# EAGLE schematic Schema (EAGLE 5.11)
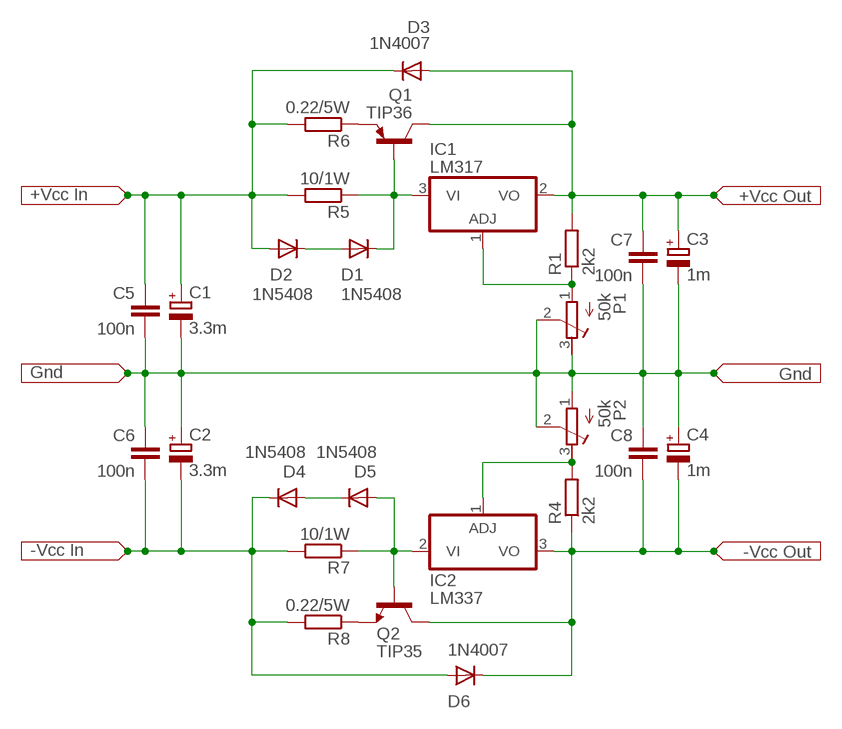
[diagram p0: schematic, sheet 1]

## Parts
C1  3.3m  CPOL-EUE3.5-8  [E3,5-8]
C2  3.3m  CPOL-EUE3.5-8  [E3,5-8]
C3  1m  CPOL-EUE3.5-8  [E3,5-8]
C4  1m  CPOL-EUE3.5-8  [E3,5-8]
C5  100n  C-EU025-060X050  [C025-060X050]
C6  100n  C-EU025-060X050  [C025-060X050]
C7  100n  C-EU025-060X050  [C025-060X050]
C8  100n  C-EU025-060X050  [C025-060X050]
D1  1N5408  1N4004  [DO41-10]
D2  1N5408  1N4004  [DO41-10]
D3  1N4007  1N4004  [DO41-10]
D4  1N5408  1N4004  [DO41-10]
D5  1N5408  1N4004  [DO41-10]
D6  1N4007  1N4004  [DO41-10]
IC1  LM317  317T  [TO220H]
IC2  LM337  337T  [TO220H]
P1  50k  R-TRIMM64W  [RTRIM64W]
P2  50k  R-TRIMM64W  [RTRIM64W]
Q1  TIP36  2N3635  [TO39]
Q2  TIP35  2N2219A  [TO39]
R1  2k2  R-EU_0207/10  [0207/10]
R4  2k2  R-EU_0207/10  [0207/10]
R5  10/1W  R-EU_0207/10  [0207/10]
R6  0.22/5W  R-EU_0207/10  [0207/10]
R7  10/1W  R-EU_0207/10  [0207/10]
R8  0.22/5W  R-EU_0207/10  [0207/10]

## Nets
N$1: IC1.1(ADJ) P1.1(E) R1.1
N$2: IC2.1(ADJ) P2.3(A) R4.2
N$3: C3.+ C7.1 D3.A IC1.2(VO) Q1.3(C) R1.2
N$4: C4.- C8.2 D6.C IC2.3(VO) Q2.3(C) R4.1
N$5: C1.- C2.+ C3.- C4.+ C5.2 C6.1 C7.2 C8.1 P1.2(S) P1.3(A) P2.1(E) P2.2(S)
N$6: D1.C IC1.3(VI) Q1.2(B) R5.1
N$7: D1.A D2.C
N$8: Q1.1(E) R6.1
N$10: C1.+ C5.1 D2.A D3.C R5.2 R6.2
N$11: Q2.1(E) R8.1
N$12: D5.A IC2.2(VI) Q2.2(B) R7.1
N$13: C2.- C6.2 D4.C D6.A R7.2 R8.2
N$14: D4.A D5.C

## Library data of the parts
C1-C4 = resistor:CPOL-EU: POLARIZED CAPACITOR, European symbol
C5-C8 = resistor:C-EU: CAPACITOR, European symbol
D1-D6 = diode:1N4004: DIODE
IC1 = linear:*317: Positive VOLTAGE REGULATOR
IC2 = linear:*337: Negative VOLTAGE REGULATOR
P1 P2 = resistor:R-TRIMM: Trimm resistor
Q1 = transistor-pnp:2N3635*: PNP Transistror
Q2 = transistor-npn:2N2219A: NPN Transistor
R1 R4-R8 = resistor:R-EU_: RESISTOR, European symbol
